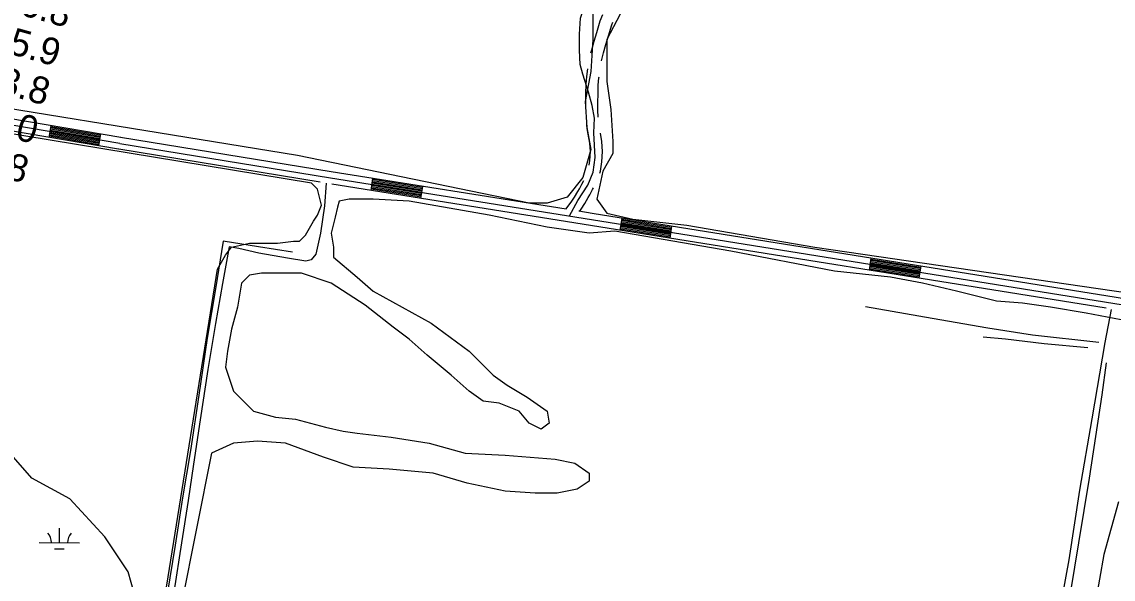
# Model space of a CAD drawing. Extents: x 3161615 to 3199515, y 867541 to 892976.
# Drawn here: x 3186975 to 3189678, y 875300 to 876681 of the extents above; entities that cross this region are included whole.
import ezdxf

# ---------------------------------------------------------------- set-up
doc = ezdxf.new("R2010")
doc.units = 0
for name, color, linetype in [('V-RIVR-RANG', 7, 'Continuous'), ('V-ROAD-CNTR', 7, 'Continuous'), ('V-SITE-VEGE', 7, 'Continuous'), ('V-TOPO-SHOR', 7, 'Continuous'), ('V-WETL-SWMP', 7, 'Continuous')]:
    doc.layers.add(name, color=color, linetype=linetype)

msp = doc.modelspace()

# ---------------------------------------------------------------- linework, layer by layer
at = {"layer": 'V-ROAD-CNTR'}
for p, q in [((3187042.2, 876394), (3187047.2, 876423.6)), ((3187165.4, 876373.1), (3187170.4, 876402.7)), ((3187840, 876262.9), (3187844.7, 876292.5)), ((3187963.4, 876243.2), (3187968.1, 876272.8)), ((3188457.1, 876164.3), (3188461.9, 876193.9)), ((3188580.5, 876144.4), (3188585.3, 876174.1)), ((3189074.2, 876065.2), (3189079, 876094.8)), ((3189197.6, 876045.4), (3189202.4, 876075))]:
    msp.add_line(p, q, dxfattribs=at)
for points in [[(3187217.2, 876379.5), (3186063.7, 876575.2), (3185238.8, 876705.3), (3184353.1, 876836.2), (3183434.5, 876974.9), (3183096.5, 877027.7), (3182832.3, 877067.9), (3182620.8, 877102.1), (3182566.6, 877107.2), (3182524.7, 877106.8), (3182470.3, 877107.4), (3181710.6, 877110.1), (3181684.7, 877112.3), (3181660.7, 877115)], [(3188331.4, 876199.6), (3188352.2, 876237.7), (3188377.1, 876276.1), (3188390.2, 876308.1), (3188395, 876344.1), (3188391.5, 876405.6), (3188393.4, 876441.8), (3188387.5, 876473), (3188378.3, 876506), (3188364.9, 876550.6), (3188358.1, 876574.5), (3188356.3, 876610.5), (3188356, 876650), (3188359.1, 876689.8), (3188371.4, 876726), (3188384.1, 876760), (3188419.7, 876856.1), (3188427.8, 876890.2), (3188423.7, 876921.6), (3188420.1, 876937), (3188423.5, 876966.4), (3188430, 877002.6), (3188436.9, 877042.4), (3188432.1, 877107.8)], [(3187219.7, 876394.3), (3186066.1, 876590), (3185383, 876697.7)], [(3188384.6, 876603.4), (3188386.6, 876611.5), (3188392.7, 876632.7), (3188399.4, 876654.3), (3188407.6, 876682.8), (3188413.9, 876698.9)], [(3188410.8, 876584.1), (3188415.6, 876603.8), (3188421.5, 876624.1), (3188428.1, 876645.7), (3188436, 876673.1), (3188438.7, 876680.1)], [(3187214.7, 876364.7), (3186061.2, 876560.4), (3185394.8, 876665.5)], [(3188372, 876464.3), (3188372, 876479.8), (3188372.3, 876503.5), (3188372.9, 876525), (3188374.6, 876545), (3188377.1, 876564.1)], [(3188402.8, 876444.7), (3188402, 876461.3), (3188402, 876479.6), (3188402.3, 876502.9), (3188402.9, 876523.3), (3188404.5, 876541.8), (3188404.8, 876544.6)], [(3187168.4, 876390.8), (3187045.2, 876411.7)], [(3187168.9, 876393.8), (3187045.7, 876414.7)], [(3187169.4, 876396.8), (3187046.2, 876417.7)], [(3187169.9, 876399.7), (3187046.7, 876420.6)], [(3188379.8, 876325.3), (3188381.6, 876337.2), (3188383.3, 876359.5), (3188381.6, 876380.2), (3188378.1, 876402.4), (3188375.6, 876415.9), (3188374.6, 876424.5)], [(3187165.9, 876376.1), (3187042.7, 876397)], [(3187166.4, 876379), (3187043.2, 876399.9)], [(3187166.9, 876382), (3187043.7, 876402.9)], [(3187167.4, 876384.9), (3187044.2, 876405.8)], [(3187167.9, 876387.9), (3187044.7, 876408.8)], [(3188323.3, 876216.1), (3187741.5, 876309), (3187219.6, 876394.3)], [(3188406.5, 876306), (3188408.1, 876310.9), (3188411.4, 876333.9), (3188413.4, 876359.6), (3188411.4, 876383.8), (3188408, 876405.1)], [(3187713.9, 876283.1), (3187214.8, 876364.7)], [(3187217.2, 876379.5), (3187739.2, 876294.2), (3188385.7, 876190.9), (3189790.2, 875965.4), (3189823, 875954.7), (3189862.7, 875938.9)], [(3187729.1, 876280.6), (3187724.3, 876224.7), (3187714.3, 876157.4), (3187703.2, 876104.7), (3187691.4, 876090.6), (3187678.3, 876088), (3187633, 876094.7), (3187562.3, 876107.3), (3187512.7, 876118.8), (3187488.1, 876123), (3187471.7, 876032.4), (3187454.8, 875933), (3187435.5, 875819), (3187416.6, 875694.7), (3187400, 875584.7), (3187387.1, 875494.5), (3187370.2, 875389.5), (3187351.1, 875267.7)], [(3189660.6, 875971), (3188383.3, 876176.1), (3187743.1, 876278.4)], [(3187965.3, 876255), (3187841.9, 876274.8)], [(3187965.8, 876258), (3187842.3, 876277.7)], [(3187966.2, 876261), (3187842.8, 876280.7)], [(3187966.7, 876263.9), (3187843.3, 876283.6)], [(3187967.2, 876266.9), (3187843.8, 876286.6)], [(3187967.7, 876269.8), (3187844.2, 876289.6)], [(3188322.5, 876216.2), (3188336, 876233.7), (3188344.1, 876245.9), (3188352.1, 876260.5), (3188356.1, 876267), (3188362, 876278.4), (3188366.6, 876287.8)], [(3187963.9, 876246.1), (3187840.4, 876265.9)], [(3187964.4, 876249.1), (3187840.9, 876268.8)], [(3187964.8, 876252.1), (3187841.4, 876271.8)], [(3188356.2, 876210.8), (3188360.4, 876216.2), (3188369.8, 876230.4), (3188378.1, 876245.5), (3188382.2, 876252.3), (3188388.8, 876264.9), (3188390.9, 876269.2)], [(3189847.7, 875961), (3189828.1, 875968.8), (3189793.7, 875980), (3188388, 876205.7), (3188354.7, 876211.1)], [(3188581, 876147.4), (3188457.6, 876167.2)], [(3188581.5, 876150.4), (3188458.1, 876170.2)], [(3188582, 876153.3), (3188458.5, 876173.2)], [(3188582.4, 876156.3), (3188459, 876176.1)], [(3188582.9, 876159.3), (3188459.5, 876179.1)], [(3188583.4, 876162.2), (3188460, 876182)], [(3188583.9, 876165.2), (3188460.5, 876185)], [(3188584.3, 876168.1), (3188460.9, 876188)], [(3188584.8, 876171.1), (3188461.4, 876190.9)], [(3189201, 876066.1), (3189077.5, 876085.9)], [(3189201.4, 876069.1), (3189078, 876088.9)], [(3189201.9, 876072), (3189078.5, 876091.8)], [(3189198.1, 876048.3), (3189074.7, 876068.1)], [(3189198.6, 876051.3), (3189075.2, 876071.1)], [(3189199.1, 876054.3), (3189075.6, 876074.1)], [(3189199.5, 876057.2), (3189076.1, 876077)], [(3189200, 876060.2), (3189076.6, 876080)], [(3189200.5, 876063.1), (3189077.1, 876083)], [(3189642.5, 875885.9), (3189478.4, 875904.6), (3189367.9, 875921.5), (3189229.9, 875945.4), (3189064.5, 875974.6)], [(3189536.4, 875167.4), (3189568.8, 875348.1), (3189595.9, 875520.3), (3189626.3, 875697.1), (3189658, 875886.4), (3189674, 875967.6)]]:
    msp.add_lwpolyline(points, dxfattribs=at)
at = {"layer": 'V-SITE-VEGE'}
for p, q in [((3188473.8, 876730.9), (3188424.3, 876636.9)), ((3188424.3, 876636.9), (3188424.3, 876532.9)), ((3188424.3, 876532.9), (3188434.2, 876463.6)), ((3188434.2, 876463.6), (3188439.1, 876384.4)), ((3187692.1, 876280.5), (3186910.4, 876409.2)), ((3188439.1, 876384.4), (3188439.1, 876354.7)), ((3188439.1, 876354.7), (3188414.4, 876310.2)), ((3188414.4, 876310.2), (3188399.5, 876240.9)), ((3187706.9, 876265.6), (3187692.1, 876280.5)), ((3187716.8, 876226), (3187706.9, 876265.6)), ((3187706.9, 876201.3), (3187716.8, 876226)), ((3187756.4, 876221.1), (3187751.4, 876196.3)), ((3187761.3, 876235.9), (3187756.4, 876221.1)), ((3187786.1, 876240.9), (3187761.3, 876235.9)), ((3187845.4, 876240.9), (3187786.1, 876240.9)), ((3187934.5, 876235.9), (3187845.4, 876240.9)), ((3188132.4, 876201.3), (3187934.5, 876235.9)), ((3188399.5, 876240.9), (3188424.3, 876206.2)), ((3187697, 876186.4), (3187706.9, 876201.3)), ((3187751.4, 876196.3), (3187741.5, 876156.7)), ((3188275.9, 876171.6), (3188132.4, 876201.3)), ((3188424.3, 876206.2), (3188488.6, 876191.4)), ((3187677.2, 876151.8), (3187697, 876186.4)), ((3188379.8, 876156.7), (3188275.9, 876171.6)), ((3188488.6, 876191.4), (3188622.2, 876176.5)), ((3188622.2, 876176.5), (3188938.8, 876122.1)), ((3187662.4, 876136.9), (3187677.2, 876151.8)), ((3187741.5, 876156.7), (3187746.5, 876122.1)), ((3188444.1, 876161.7), (3188379.8, 876156.7)), ((3188731, 876112.2), (3188444.1, 876161.7)), ((3187479.3, 876102.3), (3187494.2, 876122.1)), ((3187494.2, 876122.1), (3187538.7, 876132)), ((3187538.7, 876132), (3187608, 876132)), ((3187608, 876132), (3187647.5, 876136.9)), ((3187647.5, 876136.9), (3187662.4, 876136.9)), ((3187746.5, 876122.1), (3187746.5, 876097.3)), ((3188988.3, 876062.7), (3188731, 876112.2)), ((3188938.8, 876122.1), (3189720.5, 876008.2)), ((3187459.5, 876067.6), (3187479.3, 876102.3)), ((3187746.5, 876097.3), (3187805.9, 876047.8)), ((3187301.2, 875082.6), (3187459.5, 876067.6)), ((3189126.8, 876047.8), (3188988.3, 876062.7)), ((3187518.9, 876033), (3187509, 875973.6)), ((3187538.7, 876052.8), (3187518.9, 876033)), ((3187568.4, 876057.7), (3187538.7, 876052.8)), ((3187667.3, 876057.7), (3187568.4, 876057.7)), ((3187741.5, 876033), (3187667.3, 876057.7)), ((3187825.6, 875978.5), (3187741.5, 876033)), ((3187805.9, 876047.8), (3187845.4, 876013.2)), ((3189206, 876033), (3189126.8, 876047.8)), ((3189290.1, 876013.2), (3189206, 876033)), ((3187845.4, 876013.2), (3187988.9, 875934)), ((3189389, 875988.4), (3189290.1, 876013.2)), ((3187894.9, 875924.1), (3187825.6, 875978.5)), ((3189453.3, 875983.5), (3189389, 875988.4)), ((3189522.6, 875973.6), (3189453.3, 875983.5)), ((3187509, 875973.6), (3187494.2, 875919.1)), ((3189611.6, 875958.7), (3189522.6, 875973.6)), ((3189715.5, 875938.9), (3189611.6, 875958.7)), ((3187934.5, 875894.4), (3187894.9, 875924.1)), ((3187988.9, 875934), (3188082.9, 875864.7)), ((3187494.2, 875919.1), (3187484.3, 875864.7)), ((3187979, 875854.8), (3187934.5, 875894.4)), ((3187484.3, 875864.7), (3187479.3, 875825.1)), ((3188038.4, 875805.3), (3187979, 875854.8)), ((3188082.9, 875864.7), (3188142.3, 875805.3)), ((3187479.3, 875825.1), (3187499.1, 875765.7)), ((3188082.9, 875765.7), (3188038.4, 875805.3)), ((3188142.3, 875805.3), (3188176.9, 875780.5)), ((3187499.1, 875765.7), (3187548.6, 875716.2)), ((3188117.5, 875740.9), (3188082.9, 875765.7)), ((3188176.9, 875780.5), (3188226.4, 875750.8)), ((3188157.1, 875736), (3188117.5, 875740.9)), ((3188206.6, 875716.2), (3188157.1, 875736)), ((3188226.4, 875750.8), (3188275.9, 875716.2)), ((3187548.6, 875716.2), (3187603, 875701.3)), ((3188231.3, 875686.5), (3188206.6, 875716.2)), ((3188275.9, 875716.2), (3188280.8, 875686.5)), ((3187603, 875701.3), (3187652.5, 875696.4)), ((3187652.5, 875696.4), (3187726.7, 875676.6)), ((3188261, 875671.6), (3188231.3, 875686.5)), ((3188280.8, 875686.5), (3188261, 875671.6)), ((3187726.7, 875676.6), (3187771.2, 875666.7)), ((3187771.2, 875666.7), (3187805.9, 875661.7)), ((3187805.9, 875661.7), (3187890, 875651.8)), ((3187499.1, 875637), (3187444.7, 875612.2)), ((3187558.5, 875641.9), (3187499.1, 875637)), ((3187627.8, 875637), (3187558.5, 875641.9)), ((3187721.8, 875602.3), (3187627.8, 875637)), ((3187890, 875651.8), (3187984, 875637)), ((3187984, 875637), (3188073, 875612.2)), ((3187444.7, 875612.2), (3187365.5, 875216.2)), ((3187796, 875577.6), (3187721.8, 875602.3)), ((3188073, 875612.2), (3188172, 875607.3)), ((3188172, 875607.3), (3188295.6, 875597.4)), ((3187885, 875572.6), (3187796, 875577.6)), ((3187993.9, 875562.7), (3187885, 875572.6)), ((3188295.6, 875597.4), (3188345.1, 875587.5)), ((3188345.1, 875587.5), (3188379.8, 875562.7)), ((3188078, 875538), (3187993.9, 875562.7)), ((3188379.8, 875562.7), (3188379.8, 875542.9)), ((3188172, 875518.2), (3188078, 875538)), ((3188246.2, 875513.2), (3188172, 875518.2)), ((3188350.1, 875523.1), (3188300.6, 875513.2)), ((3188379.8, 875542.9), (3188350.1, 875523.1)), ((3188300.6, 875513.2), (3188246.2, 875513.2))]:
    msp.add_line(p, q, dxfattribs=at)
msp.add_lwpolyline([(3188389.6, 876701.2), (3188389.6, 876636.9), (3188384.7, 876557.7), (3188369.9, 876483.4), (3188374.8, 876419.1), (3188384.7, 876364.6), (3188364.9, 876295.3), (3188325.3, 876245.8), (3188275.9, 876231), (3188231.3, 876231), (3187657.4, 876349.8), (3185525.1, 876696.3)], dxfattribs=at)
at = {"layer": 'V-TOPO-SHOR'}
for points in [[(3187645.4, 876110), (3187560.7, 876123.1), (3187473.6, 876137.3), (3187454.4, 876019.5), (3187433.9, 875897.1), (3187413.5, 875756.1), (3187392.9, 875618.7), (3187372.7, 875501.4), (3187354.7, 875384), (3187334.8, 875263)], [(3189615.7, 875873.2), (3189507.5, 875882.5), (3189411.4, 875894.3), (3189356.2, 875899.4)], [(3189553.2, 875148.7), (3189593.1, 875389.8), (3189619.2, 875549.8), (3189650.8, 875756.7), (3189661.8, 875836.2)]]:
    msp.add_lwpolyline(points, dxfattribs=at)
at = {"layer": 'V-WETL-SWMP'}
for p, q in [((3186999.5, 875549.7), (3186898.2, 875665.5)), ((3187093.6, 875499), (3186999.5, 875549.7)), ((3187180.4, 875404.9), (3187093.6, 875499)), ((3189691, 875491.8), (3189654.9, 875361.4)), ((3187068, 875390.3), (3187068.1, 875426.3)), ((3187018, 875390.5), (3187118, 875390.2)), ((3187238.3, 875318), (3187180.4, 875404.9)), ((3187056, 875374.9), (3187080, 875374.9)), ((3189654.9, 875361.4), (3189633.2, 875238.3)), ((3187267.2, 875216.6), (3187238.3, 875318))]:
    msp.add_line(p, q, dxfattribs=at)
for centre, start, end in [((3187012.8, 875390.9), 359.0699, 40.6135), ((3187123.3, 875390.6), 139.0699, 180.6135)]:
    msp.add_arc(centre, 35.2, start, end, dxfattribs=at)

# ---------------------------------------------------------------- texts
at = {"layer": 'V-RIVR-RANG'}
for s, p in [('46.8', (3186918.1, 876712.3)), ('45.9', (3186891.4, 876615.9)), ('43.8', (3186865.2, 876519.4)), ('46.0', (3186836, 876423.8)), ('44.8', (3186812.3, 876326.6))]:
    msp.add_text(s, height=67, rotation=344.5183, dxfattribs=at).set_placement(p)

doc.saveas('drawing.dxf')
